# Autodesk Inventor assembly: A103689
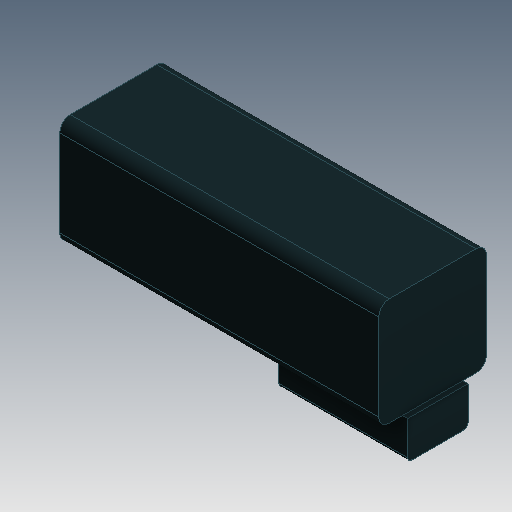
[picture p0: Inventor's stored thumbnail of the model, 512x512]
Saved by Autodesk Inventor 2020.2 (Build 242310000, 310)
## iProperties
Created: 1999-12
Part Number: A103689
Document SubType Name: Assembly
Designer: tgregory
Mass: 4775.62 g
Surface Area: 1005.51 cm^2
Volume: 1754.01 cm^3
Density: 2.72269 g/cm^3
Control State: 0
Checked Out: False
Master: False
Shininess: 0.0
Length Units: 11269
Angle Units: 11279
Time Units: 11290
Mass Units: 11283
Length Display Precision: 3
Angle Display Precision: 2
Compacted: True
Dimensions: 111x82x277 mm
Mass: 4,776 kg
Density: 0.0
Volumn: 0.0
Area: 0.0
PropertySet Name: Model Information
Author: tgregory
Revision Number: -
Title: A103689
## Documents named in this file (3)
- D:\07 - DEMODATEN\OTX 2019 - Dataset - UPDATE - Dez2019\Designs\07-Packing machine\A103689.iam
- D:\07 - DEMODATEN\OTX 2019 - Dataset - UPDATE - Dez2019\Designs\07-Packing machine\Parts\ADSK-011767.ipt
- D:\07 - DEMODATEN\OTX 2019 - Dataset - UPDATE - Dez2019\Designs\07-Packing machine\Parts\ADSK-011766.ipt
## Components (2 placed, 2 different names)
1. ADSK-011766:1 — Flush:4, Mate:1, Flush:1, Flush:2, Flush:3
2. ADSK-011767:1 — Flush:4, Mate:1
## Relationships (5: Flush 4, Mate 1)
- Flush:4: ADSK-011766:1 ↔ ADSK-011767:1
- Mate:1: ADSK-011766:1 ↔ ADSK-011767:1
- Flush:1: ADSK-011766:1
- Flush:2: ADSK-011766:1
- Flush:3: ADSK-011766:1
